Omron CX-Programmer project NewProject (CX-Programmer 6.11)

# PLC NewPLC1: CPM2* 

## Global symbols (name address type ; comment)
0.00 BOOL  ; Törlés
AR8.00 BOOL  ; Normális
AR8.01 BOOL  ; paritáshiba
AR8.02 BOOL  ; Formátumhiba
AR8.03 BOOL  ; Túlcsordulás
AR8.08 BOOL  ; Normális
AR8.09 BOOL  ; Paritás hiba
AR8.10 BOOL  ; Formátum hiba
AR8.11 BOOL  ; túlcsordulás
DM0 CHANNEL  ; uc Parancs

## Program NewProgram1 (no task)
; Megcsináltam a változtatást mégértem is valamannyire, de a DM területre nem irja ki az adatokat.

### Section Section1

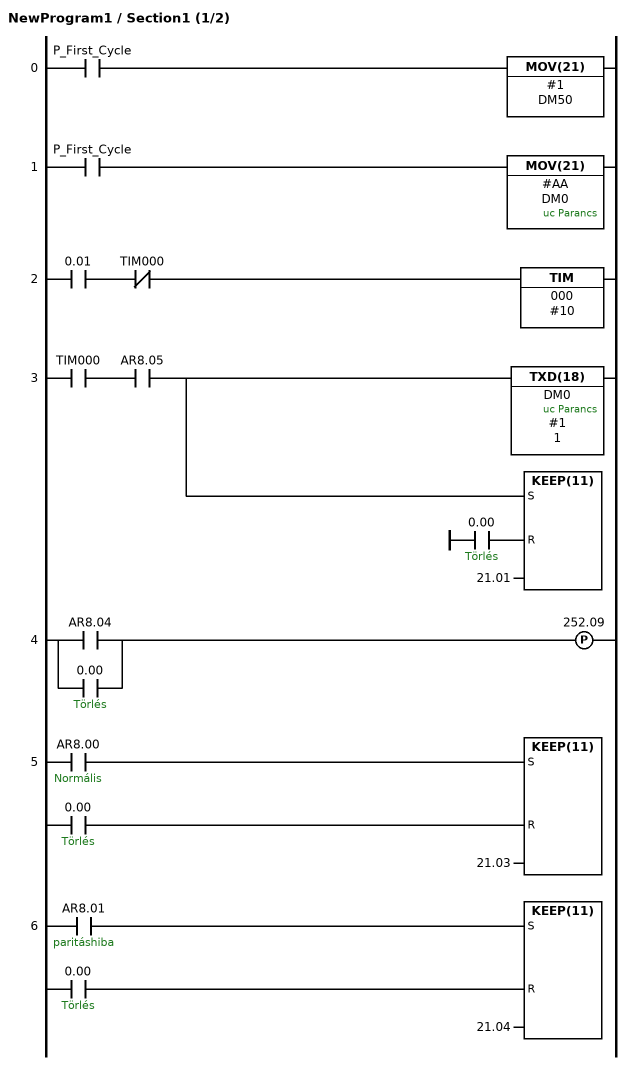
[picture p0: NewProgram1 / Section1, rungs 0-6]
; rung 0
LD P_First_Cycle
MOV(21) #1 DM50
; rung 1
LD P_First_Cycle
MOV(21) #AA DM0  ; uc Parancs
; rung 2
LD 0.01
ANDNOT TIM000
TIM 000 #10
; rung 3
LD TIM000
AND AR8.05
TXD(18) DM0 #1 1  ; uc Parancs
LD 0.00  ; Törlés
KEEP(11) 21.01
; rung 4
LD AR8.04
OR 0.00  ; Törlés
DIFU(13) 252.09
; rung 5
LD AR8.00  ; Normális
LD 0.00  ; Törlés
KEEP(11) 21.03
; rung 6
LD AR8.01  ; paritáshiba
LD 0.00  ; Törlés
KEEP(11) 21.04

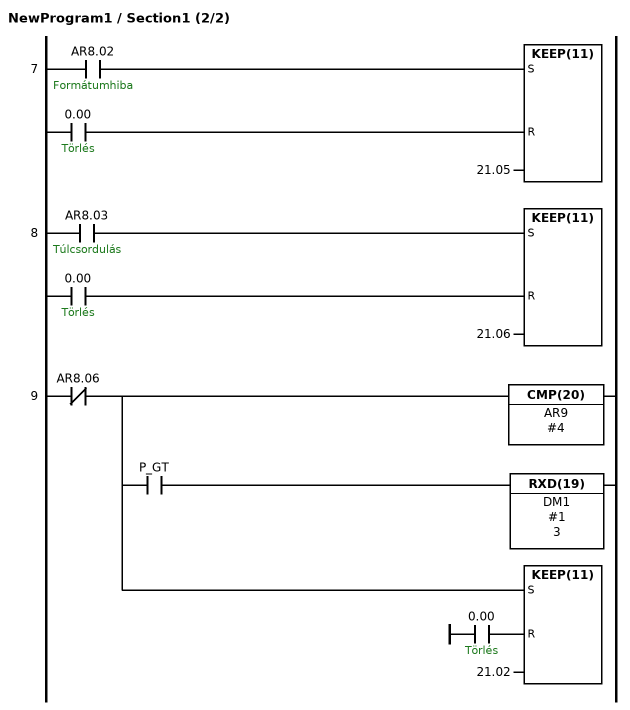
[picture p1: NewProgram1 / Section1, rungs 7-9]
; rung 7
LD AR8.02  ; Formátumhiba
LD 0.00  ; Törlés
KEEP(11) 21.05
; rung 8
LD AR8.03  ; Túlcsordulás
LD 0.00  ; Törlés
KEEP(11) 21.06
; rung 9
LDNOT AR8.06
OUT TR0
CMP(20) AR9 #4
AND P_GT
RXD(19) DM1 #1 3
LD TR0
LD 0.00  ; Törlés
KEEP(11) 21.02
; rung 10
END(01)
